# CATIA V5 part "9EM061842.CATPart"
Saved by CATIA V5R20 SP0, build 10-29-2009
Part number: 9EM061842
Revision: ANY
Definition: UNKNOWN
Nomenclature: 9EM061842
Source: Unknown
Bounding box of the stored display mesh (mm): x -9 to 9, y -9 to 9, z 0 to 42
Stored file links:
  C:\Users\Utente\Desktop\IO LAVORO\3D X SITO CF\X SITO\3D files UM\UM064242 PRODUCT\9EM061842.CATPart
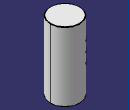
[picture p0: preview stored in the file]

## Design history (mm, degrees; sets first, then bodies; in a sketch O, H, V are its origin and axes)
Body1 "Taladro de diámetro de Ø3.5 (3.5)7" (main body)
  Solid1: solid without history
